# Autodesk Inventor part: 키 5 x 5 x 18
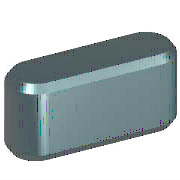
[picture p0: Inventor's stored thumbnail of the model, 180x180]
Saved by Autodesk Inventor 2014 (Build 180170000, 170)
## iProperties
Created: 2012-02
Part Number: 키 5 x 5 x 18
Material: 강철, 연강
Description: 키 및 해당 키홈
Document SubType Name: Modeling
Standard: KS B 1311
Designer: P15F
Standards Organization: KS
Language: ko-KR
Size Designation: 5 x 5 x 18
Categories: <MemberInstance><Categories><Category DisplayName="샤프트 부품" InternalName="7f7aeb1f-a693-4053-b835-cee3144e0d98" Mnemonic="SHFT"><Category DisplayName="키" Interna
Density: 1 g/cm^3
Appearance: 노란색
IsCustomPart: 1
Author: P15F
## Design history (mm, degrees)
workplane "Work Plane1"
workplane "Work Plane2"
sketch "스케치1"
  geometry: L1 (2.5, 2.5)-(15.5, 2.5); L2 (15.5, -2.5)-(2.5, -2.5); L3 (0, 9.4)-(0, -7.4) reference; L4 (-5, 0)-(30, 0) reference; L5 (18, 0)-(18, 7); A1 r 2.5 centre (2.5, 0) between (2.5, 2.5) and (2.5, -2.5); A2 r 2.5 centre (15.5, 0) between (15.5, -2.5) and (15.5, 2.5)
  constraints: 6 end point, 5 point on circle, 4 tangent, 3 point on line, 2 centre point, 1 horizontal, 1 parallel, 1 perpendicular
  dimensions: "d0" = 2.5 radius of A1 (= 0.5 x PB); "d13" = 2.5 radius of A2 (= 0.5 x PB); "d14" = 18 distance between parallel lines of L5 L3 (= NLG)
extrude "본체1" new body sketch "스케치1" taper "d3" = 0 deg; stored distance "d4" = 10
workplane "Work Plane3"
body "Solid1"
chamfer "모따기1" distance "d8" = 0.4 (= PHH); stored, may be unused: second distance "d9" = 0.4 (= PHH), angle "d15" = 45 deg
other parameters: "d1" = -3 (= -PNT), "d2" = 2 (= PH - PNT), "NLG" = 18 [user parameter; used in 3 equation terms], "PB" = 5 [user parameter; used in 2 equation terms], "PNT" = 3 [user parameter; used in 2 equation terms], "PH" = 5 [user parameter; used in 1 equation term], "PHH" = 0.4 [user parameter; used in 2 equation terms], "d10" = 0, "d16" = 0, "d17" = 0, "d18" = 0, "WDMIN" = 12 [user parameter], "PLB2" = 18 (= NLG) [user parameter], "WDMAX" = 17 [user parameter], "PLB1" = 18 (= NLG) [user parameter], "RR" = 0.16 [user parameter], "PUEB" = 2.3 [user parameter]
